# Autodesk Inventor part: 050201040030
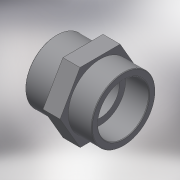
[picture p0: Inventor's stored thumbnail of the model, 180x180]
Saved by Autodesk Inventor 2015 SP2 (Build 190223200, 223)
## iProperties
Created: 2017-10
Part Number: 050201040030
Material: Generic
Description: PLASSON THREADED REDUCER PVC 4"-3"F
Document SubType Name: Modeling
Designer: KIM
Density: 1 g/cm^3
Appearance: Default
Author: KIM
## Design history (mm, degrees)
derived "050201.ipt"
feature "Solid1::050201.ipt"
tag "TaggingFeature1"
body "Solid1"
other parameters: "d0" = 86, "d1" = 84.926, "d4" = 67.9408, "d5" = 25, "d6" = 42, "d8" = 113.03, "d10" = 42, "d13" = 0, "d14" = 1.1303, "d16" = 90.424, "d17" = 110.4038, "R_" = 113.03, "lt_" = 42, "H_" = 86, "G_" = 84.926, "lt_1" = 25
